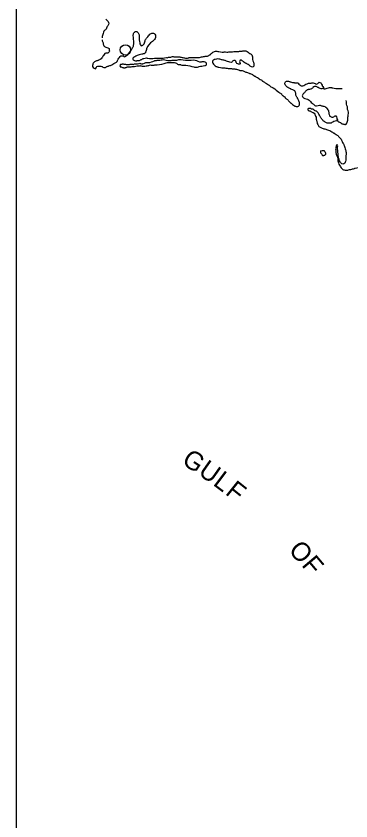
# Model space of a CAD drawing. Extents: x 452225 to 584229, y 1232161 to 1334160.
# Drawn here: x 542976 to 550729, y 1306109 to 1324758 of the extents above; entities that cross this region are included whole.
import ezdxf

# ---------------------------------------------------------------- set-up
doc = ezdxf.new("R2010")
doc.units = 0
doc.layers.add('V-ANNO-SYMB', color=7, linetype='Continuous')

msp = doc.modelspace()

# ---------------------------------------------------------------- linework, layer by layer
at = {"layer": 'V-ANNO-SYMB'}
msp.add_line((542976, 1328089), (542976, 1301350), dxfattribs=at)
msp.add_circle((545506, 1323974), 121, dxfattribs=at)
for points in [[(545050, 1324685), (545080, 1324664), (545108, 1324632), (545120, 1324591), (545109, 1324546), (545086, 1324521), (545044, 1324438), (545019, 1324424), (544999, 1324384), (544985, 1324329), (544972, 1324285), (544971, 1324254)], [(544969, 1324207), (544977, 1324169), (544988, 1324136), (544993, 1324109), (545009, 1324072), (545025, 1324055), (545052, 1324039), (545101, 1324023), (545128, 1324007), (545133, 1323969), (545133, 1323929), (545112, 1323912), (545085, 1323896), (545052, 1323896), (544985, 1323826), (544963, 1323791), (544926, 1323753), (544882, 1323737), (544866, 1323726), (544839, 1323721), (544774, 1323686), (544753, 1323653), (544747, 1323615), (544747, 1323594), (544785, 1323551), (544812, 1323540), (544845, 1323588), (544899, 1323599), (544920, 1323599), (544958, 1323594), (544985, 1323578), (545028, 1323564), (545055, 1323575), (545077, 1323591), (545098, 1323596), (545125, 1323607), (545196, 1323629), (545239, 1323659), (545298, 1323691), (545325, 1323729), (545341, 1323761), (545368, 1323799), (545401, 1323834), (545439, 1323839), (545466, 1323829), (545482, 1323818), (545514, 1323829), (545530, 1323845), (545547, 1323850), (545579, 1323883), (545665, 1324010), (545698, 1324080), (545698, 1324217), (545690, 1324325), (545695, 1324355), (545717, 1324382), (545727, 1324393), (545754, 1324404), (545787, 1324388), (545822, 1324323), (545822, 1324307), (545827, 1324274), (545827, 1324207), (545838, 1324136), (545881, 1324072), (545898, 1324077), (545925, 1324099), (545962, 1324188), (545995, 1324247), (546011, 1324263), (546070, 1324336), (546103, 1324358), (546141, 1324363), (546173, 1324358), (546200, 1324315), (546205, 1324293), (546195, 1324236), (546132, 1324172), (545997, 1324001), (545976, 1323920), (545960, 1323896), (545916, 1323880), (545884, 1323875), (545776, 1323842), (545749, 1323826), (545679, 1323775), (545684, 1323748), (545717, 1323731), (545760, 1323721), (545781, 1323726), (545835, 1323731)], [(545835, 1323731), (545857, 1323745), (545889, 1323756), (545906, 1323767), (545933, 1323777), (545997, 1323788), (546030, 1323783), (546178, 1323780), (546216, 1323785), (546378, 1323785), (546448, 1323796), (546492, 1323796), (546524, 1323810), (546556, 1323810), (546594, 1323821), (546627, 1323815), (546764, 1323815), (546802, 1323804), (546840, 1323799), (546878, 1323788), (546969, 1323791), (546986, 1323796), (547142, 1323796), (547196, 1323802), (547223, 1323802), (547318, 1323821), (547356, 1323826), (547372, 1323831), (547388, 1323831), (547458, 1323858), (547474, 1323869), (547496, 1323893), (547534, 1323920), (547572, 1323937), (547674, 1323937), (547744, 1323926), (547782, 1323926), (547804, 1323929), (547852, 1323923), (547879, 1323923), (547923, 1323929), (547950, 1323929), (548020, 1323939), (548130, 1323939), (548163, 1323947), (548190, 1323947), (548228, 1323953), (548292, 1323953), (548325, 1323937), (548368, 1323904), (548433, 1323861), (548452, 1323753), (548484, 1323621), (548468, 1323583), (548425, 1323583), (548322, 1323653), (548301, 1323659), (548252, 1323691), (548241, 1323702), (548211, 1323723), (548174, 1323740), (548157, 1323723), (548157, 1323683), (548166, 1323650), (548144, 1323645), (548109, 1323650), (548076, 1323677), (548071, 1323694), (548049, 1323726), (547995, 1323721), (547974, 1323694), (547871, 1323710), (547833, 1323721), (547806, 1323731), (547731, 1323748), (547696, 1323758), (547588, 1323756), (547523, 1323713), (547563, 1323626), (547612, 1323594), (547634, 1323583), (547671, 1323572), (547742, 1323561), (547779, 1323561), (547887, 1323545), (547941, 1323545), (548020, 1323534), (548058, 1323532), (548106, 1323521), (548139, 1323505), (548155, 1323499)], [(545468, 1323648), (545544, 1323637), (545582, 1323637), (545614, 1323642), (545652, 1323645), (545684, 1323640), (545717, 1323650), (545760, 1323650), (545822, 1323661), (545860, 1323661), (545876, 1323650), (545898, 1323650), (545919, 1323656), (545935, 1323656), (545962, 1323675), (546000, 1323680), (546141, 1323707), (546178, 1323723), (546200, 1323729), (546216, 1323729), (546243, 1323737), (546308, 1323737), (546357, 1323748), (546421, 1323748), (546551, 1323726), (546629, 1323740), (546662, 1323734), (546694, 1323740), (546899, 1323740), (546942, 1323734), (547121, 1323737), (547253, 1323699), (547285, 1323704), (547323, 1323704), (547361, 1323694), (547377, 1323645), (547366, 1323613), (547345, 1323602), (547210, 1323583), (547167, 1323567), (547129, 1323567), (547102, 1323572), (546905, 1323615), (546845, 1323615), (546802, 1323621), (546786, 1323632), (546753, 1323629), (546721, 1323640), (546699, 1323656), (546645, 1323672), (546581, 1323672), (546537, 1323677), (546505, 1323677), (546443, 1323667), (546243, 1323621), (546195, 1323621), (546168, 1323615), (546060, 1323615), (546027, 1323602), (545984, 1323596), (545881, 1323596), (545849, 1323602), (545800, 1323596), (545779, 1323596), (545714, 1323583), (545673, 1323583), (545636, 1323578), (545603, 1323578), (545565, 1323572), (545538, 1323572)], [(545403, 1323640), (545401, 1323637), (545387, 1323629), (545382, 1323615), (545382, 1323596), (545387, 1323583), (545406, 1323580), (545436, 1323569), (545449, 1323567), (545463, 1323561), (545498, 1323561), (545511, 1323567), (545538, 1323572)], [(545403, 1323640), (545417, 1323642), (545430, 1323648), (545444, 1323650), (545468, 1323648)], [(548155, 1323499), (548263, 1323478), (548295, 1323461), (548333, 1323451), (548373, 1323434), (548395, 1323429), (548433, 1323413), (548460, 1323397), (548498, 1323370), (548514, 1323364), (548546, 1323343), (548568, 1323332), (548606, 1323305), (548652, 1323278), (548673, 1323262), (548684, 1323251), (548716, 1323235), (548743, 1323213), (548776, 1323197), (548819, 1323164), (548846, 1323148), (548862, 1323132), (548930, 1323094), (549059, 1322992), (549097, 1322970), (549119, 1322954), (549129, 1322938), (549151, 1322921), (549162, 1322911), (549197, 1322884), (549224, 1322851), (549246, 1322835), (549300, 1322776), (549332, 1322749), (549348, 1322738), (549375, 1322711), (549421, 1322678), (549448, 1322668), (549480, 1322662), (549513, 1322673), (549529, 1322684), (549540, 1322727), (549540, 1322754), (549526, 1322792), (549510, 1322822), (549499, 1322838), (549489, 1322865), (549467, 1322897), (549456, 1322924), (549440, 1323011), (549383, 1323048), (549340, 1323065), (549329, 1323075), (549297, 1323086), (549275, 1323102), (549259, 1323108), (549232, 1323135), (549200, 1323205), (549216, 1323237), (549237, 1323251), (549264, 1323251), (549302, 1323245), (549324, 1323235), (549378, 1323218), (549416, 1323218), (549437, 1323213), (549480, 1323213), (549507, 1323202), (549545, 1323164), (549580, 1323143), (549613, 1323143), (549661, 1323164), (549775, 1323205), (549791, 1323205), (549823, 1323210), (549856, 1323210), (549899, 1323200), (549926, 1323183), (549964, 1323200), (549996, 1323224), (550029, 1323208), (550061, 1323156), (550066, 1323140), (550077, 1323129)], [(550077, 1323129), (550096, 1323086), (550058, 1323075), (550018, 1323081), (549991, 1323092), (549975, 1323102), (549953, 1323108), (549921, 1323124), (549888, 1323129), (549850, 1323102), (549840, 1323092), (549813, 1323073), (549791, 1323062), (549742, 1323056), (549715, 1323046), (549688, 1323024), (549661, 1322992), (549640, 1322970), (549602, 1322913), (549613, 1322881), (549659, 1322849), (549723, 1322832), (549794, 1322778), (549831, 1322741), (549864, 1322714), (549891, 1322687), (549934, 1322681), (550002, 1322692), (550034, 1322687), (550066, 1322676), (550099, 1322673), (550142, 1322651), (550153, 1322641), (550169, 1322630), (550180, 1322606), (550207, 1322568), (550220, 1322492), (550231, 1322460), (550242, 1322438), (550269, 1322427), (550312, 1322417), (550350, 1322438), (550377, 1322444), (550404, 1322395)], [(550077, 1323129), (550101, 1323075), (550177, 1323086), (550236, 1323100), (550280, 1323100), (550296, 1323094), (550312, 1323094), (550377, 1323083), (550523, 1323083)], [(550404, 1322395), (550415, 1322341), (550447, 1322309), (550488, 1322292), (550525, 1322265), (550558, 1322255), (550590, 1322249), (550623, 1322255), (550644, 1322298), (550655, 1322344), (550660, 1322392), (550660, 1322414), (550663, 1322435), (550663, 1322562), (550652, 1322595), (550652, 1322627), (550647, 1322654), (550636, 1322687), (550623, 1322800)], [(550404, 1322395), (550415, 1322336), (550361, 1322325), (550269, 1322279), (550193, 1322279), (550166, 1322284), (550134, 1322300), (550096, 1322327), (550085, 1322338), (550034, 1322403), (549969, 1322514), (549937, 1322546), (549921, 1322557), (549888, 1322573), (549850, 1322600), (549815, 1322603), (549799, 1322614), (549783, 1322614), (549745, 1322619), (549729, 1322603), (549745, 1322570), (549764, 1322565), (549791, 1322554), (549813, 1322538), (549856, 1322522), (549894, 1322484), (549904, 1322462), (549921, 1322419), (549926, 1322398), (549931, 1322349), (549939, 1322327), (549945, 1322290), (549961, 1322244), (549977, 1322217), (550004, 1322190), (550064, 1322163), (550145, 1322136), (550185, 1322125), (550288, 1322079), (550320, 1322057), (550342, 1322047), (550385, 1322014), (550412, 1321998), (550434, 1321982), (550450, 1321960), (550485, 1321925), (550501, 1321904), (550550, 1321806), (550566, 1321785), (550571, 1321763), (550606, 1321661), (550617, 1321577), (550617, 1321544), (550612, 1321517), (550612, 1321447), (550601, 1321388), (550585, 1321353), (550542, 1321331), (550504, 1321353), (550477, 1321380), (550444, 1321490), (550434, 1321539), (550434, 1321577), (550425, 1321609), (550425, 1321636), (550420, 1321669), (550420, 1321706), (550409, 1321774), (550393, 1321769), (550388, 1321733), (550377, 1321701), (550377, 1321663), (550382, 1321620), (550382, 1321598), (550423, 1321450), (550423, 1321423), (550434, 1321380), (550477, 1321283), (550506, 1321245), (550555, 1321196), (550593, 1321191), (550658, 1321191), (550695, 1321202), (550728, 1321207), (550809, 1321229), (550830, 1321237), (550901, 1321247), (550938, 1321247), (550971, 1321258), (551046, 1321269), (551109, 1321269)], [(550053, 1321642), (550107, 1321642), (550118, 1321631), (550134, 1321604), (550142, 1321561), (550131, 1321544), (550115, 1321528), (550099, 1321528)], [(550037, 1321642), (550029, 1321628), (550026, 1321612), (550031, 1321585), (550045, 1321569), (550061, 1321542), (550074, 1321531), (550099, 1321528)]]:
    msp.add_spline(points, degree=3, dxfattribs=at)

# ---------------------------------------------------------------- texts
for s, rotation, p in [('G', 326.9162, (546789, 1314395)), ('U', 324.8526, (547170, 1314147)), ('L', 322.9366, (547515, 1313905)), ('F', 321.3158, (547800, 1313692)), ('O', 312.3292, (549266, 1312367)), ('F', 310.2656, (549572, 1312032))]:
    msp.add_text(s, height=432, rotation=rotation, dxfattribs=at).set_placement(p)

doc.saveas('drawing.dxf')
